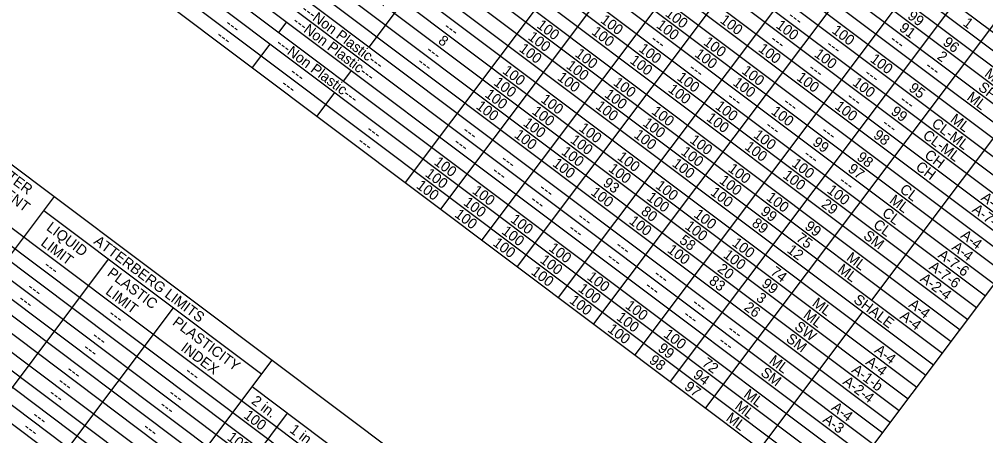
# Model space of a CAD drawing. Extents: x 627484.2 to 627517.5, y 367968.7 to 367996.9.
# Drawn here: x 627506.06 to 627511.18, y 367976.4 to 367978.6 of the extents above; entities that cross this region are included whole.
import ezdxf

# ---------------------------------------------------------------- set-up
doc = ezdxf.new("R2010")
doc.units = 0
doc.layers.add('Default', color=7, linetype='Continuous')

msp = doc.modelspace()

# ---------------------------------------------------------------- linework, layer by layer
at = {"layer": 'Default'}
for p, q in [((627507.3424, 367981.3499), (627511.8177, 367977.9894)), ((627507.3014, 367981.2954), (627511.7767, 367977.9348)), ((627507.2546, 367981.233), (627511.7298, 367977.8725)), ((627507.2078, 367981.1706), (627511.683, 367977.8101)), ((627507.1609, 367981.1082), (627511.6362, 367977.7477)), ((627507.1199, 367981.0537), (627511.5952, 367977.6932)), ((627507.0731, 367980.9913), (627511.5483, 367977.6308)), ((627507.0263, 367980.9289), (627511.5015, 367977.5684)), ((627506.9794, 367980.8665), (627511.4547, 367977.506)), ((627506.9326, 367980.8042), (627511.4078, 367977.4437)), ((627506.8858, 367980.7418), (627511.361, 367977.3813)), ((627506.8448, 367980.6872), (627511.32, 367977.3267)), ((627506.7979, 367980.6248), (627511.2732, 367977.2643)), ((627506.7511, 367980.5625), (627511.2264, 367977.202)), ((627506.7043, 367980.5001), (627511.1795, 367977.1396)), ((627506.6574, 367980.4377), (627511.1327, 367977.0772)), ((627506.6106, 367980.3754), (627511.0858, 367977.0149)), ((627506.5696, 367980.3208), (627511.0449, 367976.9603)), ((627506.5228, 367980.2584), (627510.998, 367976.8979)), ((627506.4759, 367980.196), (627510.9512, 367976.8355)), ((627506.4291, 367980.1337), (627510.9044, 367976.7732)), ((627506.3881, 367980.0791), (627510.8634, 367976.7186)), ((627508.1067, 367977.74), (627509.8689, 367980.0868)), ((627506.3413, 367980.0167), (627510.8165, 367976.6562)), ((627506.2944, 367979.9543), (627510.7697, 367976.5938)), ((627506.2476, 367979.892), (627510.7229, 367976.5315)), ((627506.2008, 367979.8296), (627510.676, 367976.4691)), ((627506.1598, 367979.775), (627510.635, 367976.4145)), ((627507.914, 367978.4577), (627508.9152, 367979.791)), ((627508.2938, 367977.5995), (627509.9506, 367979.806)), ((627506.113, 367979.7126), (627510.5882, 367976.3521)), ((627506.0661, 367979.6503), (627510.5414, 367976.2898)), ((627508.5121, 367977.4356), (627510.1689, 367979.642)), ((627506.0251, 367979.5957), (627510.5004, 367976.2352)), ((627505.9783, 367979.5333), (627510.4536, 367976.1728)), ((627505.9315, 367979.4709), (627510.4067, 367976.1104)), ((627508.6992, 367977.2951), (627510.356, 367979.5015)), ((627505.8846, 367979.4086), (627510.3599, 367976.0481)), ((627508.9175, 367977.1312), (627510.5743, 367979.3376)), ((627509.1046, 367976.9907), (627510.7615, 367979.1971)), ((627509.3229, 367976.8267), (627510.9798, 367979.0332)), ((627510.6092, 367978.9944), (627511.8645, 367978.0518)), ((627509.51, 367976.6862), (627511.1669, 367978.8927)), ((627509.6972, 367976.5457), (627511.4594, 367978.8925)), ((627510.577, 367977.1165), (627511.7479, 367978.6759)), ((627507.4363, 367978.536), (627507.4773, 367978.5906)), ((627505.1779, 367978.4674), (627509.6531, 367975.1069)), ((627507.2958, 367978.3489), (627507.3895, 367978.4737)), ((627510.3599, 367976.0481), (627512.1221, 367978.3948)), ((627507.7794, 367978.2784), (627507.8204, 367978.333)), ((627505.0169, 367978.253), (627509.4921, 367974.8925)), ((627504.97, 367978.1906), (627509.4453, 367974.8301)), ((627507.6389, 367978.0913), (627507.7325, 367978.2161)), ((627504.9291, 367978.136), (627509.4043, 367974.7755)), ((627504.8822, 367978.0736), (627509.3575, 367974.7131)), ((627504.8354, 367978.0113), (627509.3106, 367974.6508)), ((627504.7944, 367977.9567), (627509.2696, 367974.5962)), ((627504.7476, 367977.8943), (627509.2228, 367974.5338)), ((627504.7007, 367977.8319), (627509.176, 367974.4714)), ((627504.6539, 367977.7696), (627509.1291, 367974.4091)), ((627504.6129, 367977.715), (627509.0882, 367974.3545)), ((627504.4574, 367975.2834), (627506.246, 367977.6653)), ((627504.5661, 367977.6526), (627509.0413, 367974.2921)), ((627504.5192, 367977.5902), (627508.9945, 367974.2297)), ((627506.1904, 367977.5912), (627507.3443, 367976.7248)), ((627505.8894, 367976.476), (627506.5334, 367977.3336)), ((627506.2325, 367976.2184), (627506.8765, 367977.076)), ((627509.9856, 367976.3291), (627510.5301, 367977.0542)), ((627505.6113, 367974.417), (627507.3999, 367976.7988)), ((627507.2945, 367976.6585), (627508.885, 367975.4642)), ((627505.7985, 367974.2765), (627507.4816, 367976.518))]:
    msp.add_line(p, q, dxfattribs=at)

# ---------------------------------------------------------------- texts
for s, p in [('---Non Plastic---', (627507.5506, 367978.6475)), ('100', (627509.4783, 367978.6265)), ('99', (627510.7623, 367978.6134)), ('---Non Plastic---', (627507.5038, 367978.5851)), ('100', (627508.7977, 367978.5645)), ('100', (627509.1351, 367978.5916)), ('100', (627509.4314, 367978.5642)), ('100', (627509.7688, 367978.5913)), ('100', (627510.0652, 367978.5638)), ('---', (627510.1284, 367978.6139)), ('1', (627511.056, 367978.5757)), ('---', (627507.1469, 367978.5727)), ('---', (627508.3051, 367978.5564)), ('100', (627509.0882, 367978.5293)), ('100', (627510.3616, 367978.5363)), ('91', (627510.718, 367978.5491)), ('---', (627507.1, 367978.5103)), ('8', (627508.2751, 367978.4814)), ('100', (627508.7509, 367978.5022)), ('---', (627509.401, 367978.4895)), ('100', (627509.681, 367978.4743)), ('---', (627510.0348, 367978.4891)), ('---', (627510.6685, 367978.4887)), ('96', (627510.9492, 367978.473)), ('---Non Plastic---', (627507.416, 367978.4681)), ('---', (627508.2115, 367978.4317)), ('100', (627508.704, 367978.4398)), ('100', (627509.0004, 367978.4123)), ('100', (627509.3378, 367978.4394)), ('100', (627509.6342, 367978.4119)), ('100', (627509.9715, 367978.4391)), ('100', (627510.2679, 367978.4116)), ('---', (627510.3311, 367978.4616)), ('100', (627509.2909, 367978.377)), ('100', (627510.5643, 367978.3841)), ('2', (627510.9187, 367978.3984)), ('---', (627508.1646, 367978.3693)), ('100', (627508.6162, 367978.3228)), ('100', (627508.9536, 367978.3499)), ('---', (627509.6037, 367978.3373)), ('100', (627509.8837, 367978.3221)), ('---', (627510.2375, 367978.3369)), ('---', (627510.8556, 367978.3482)), ('ML', (627511.1703, 367978.3071)), ('---', (627507.4899, 367978.3151)), ('100', (627508.5694, 367978.2605)), ('100', (627508.9067, 367978.2876)), ('100', (627509.2031, 367978.2601)), ('100', (627509.5405, 367978.2872)), ('100', (627509.8369, 367978.2597)), ('100', (627510.1742, 367978.2868)), ('100', (627510.4706, 367978.2594)), ('---', (627510.5339, 367978.3094)), ('---', (627507.4431, 367978.2527)), ('100', (627509.4936, 367978.2248)), ('95', (627510.7686, 367978.2307)), ('SP', (627511.1365, 367978.2349)), ('100', (627508.5225, 367978.1981)), ('100', (627508.8189, 367978.1706)), ('100', (627509.1563, 367978.1977)), ('---', (627509.8064, 367978.185)), ('---', (627510.4402, 367978.1847)), ('---', (627510.721, 367978.1689)), ('ML', (627511.0766, 367978.1823)), ('100', (627508.4757, 367978.1357)), ('100', (627508.7721, 367978.1082)), ('100', (627509.1094, 367978.1354)), ('100', (627509.4058, 367978.1079)), ('100', (627509.7432, 367978.135)), ('100', (627510.0396, 367978.1075)), ('---', (627510.1028, 367978.1576)), ('100', (627510.3769, 367978.1346)), ('99', (627510.6742, 367978.1065)), ('100', (627509.6964, 367978.0726)), ('ML', (627510.9888, 367978.0654)), ('100', (627508.7252, 367978.0459)), ('100', (627509.0216, 367978.0184)), ('100', (627509.359, 367978.0455)), ('---', (627510.0091, 367978.0328)), ('---', (627510.6273, 367978.0442)), ('CL-ML', (627510.8896, 367978.0423)), ('---', (627507.8953, 367978.0106)), ('---', (627508.4043, 367978.0065)), ('100', (627508.6784, 367977.9835)), ('100', (627508.9748, 367977.956)), ('100', (627509.3122, 367977.9831)), ('100', (627509.6085, 367977.9557)), ('100', (627509.9459, 367977.9828)), ('99', (627510.2588, 367977.9429)), ('---', (627510.3055, 367978.0053)), ('98', (627510.581, 367977.9814)), ('CL-ML', (627510.8428, 367977.9799)), ('---', (627507.8485, 367977.9483)), ('---', (627508.3574, 367977.9441)), ('100', (627509.8991, 367977.9204)), ('WATER', (627505.8921, 367977.8322)), ('100', (627508.9279, 367977.8937)), ('100', (627509.2243, 367977.8662)), ('100', (627509.5617, 367977.8933)), ('---', (627510.2119, 367977.8806)), ('98', (627510.4932, 367977.8644)), ('CH', (627510.8518, 367977.8756)), ('CONTENT', (627505.8061, 367977.7936)), ('100', (627508.2532, 367977.8395)), ('---', (627508.607, 367977.8542)), ('100', (627508.8811, 367977.8313)), ('100', (627509.1775, 367977.8038)), ('100', (627509.5149, 367977.8309)), ('100', (627509.8112, 367977.8034)), ('100', (627510.1486, 367977.8305)), ('97', (627510.4459, 367977.8024)), ('CH', (627510.805, 367977.8132)), ('100', (627508.2064, 367977.7771)), ('---', (627508.5602, 367977.7919)), ('100', (627509.7644, 367977.7411)), ('100', (627510.1018, 367977.7682)), ('100', (627508.1595, 367977.7147)), ('93', (627509.1485, 367977.7281)), ('100', (627509.427, 367977.714)), ('100', (627510.3357, 367977.69)), ('---', (627510.399, 367977.7401)), ('CL', (627510.7208, 367977.6935)), ('100', (627508.4559, 367977.6872)), ('---', (627508.8097, 367977.702)), ('100', (627509.0838, 367977.6791)), ('100', (627509.3802, 367977.6516)), ('100', (627509.7176, 367977.6787)), ('100', (627510.014, 367977.6512)), ('ML', (627510.6668, 367977.6366)), ('A-7-6', (627511.1513, 367977.6507)), ('100', (627508.4091, 367977.6249)), ('---', (627508.7629, 367977.6396)), ('29', (627510.3054, 367977.6153)), ('A-7-6', (627511.1045, 367977.5883)), ('100', (627508.3623, 367977.5625)), ('80', (627509.3496, 367977.577)), ('100', (627509.6298, 367977.5617)), ('99', (627509.9836, 367977.5765)), ('CL', (627510.6271, 367977.5688)), ('LIQUID', (627506.1996, 367977.4918)), ('100', (627508.6586, 367977.535)), ('---', (627509.0124, 367977.5498)), ('100', (627509.2865, 367977.5268)), ('100', (627509.5829, 367977.4994)), ('89', (627509.9368, 367977.5141)), ('99', (627510.2176, 367977.4983)), ('CL', (627510.5803, 367977.5064)), ('100', (627508.6118, 367977.4726)), ('---', (627508.9656, 367977.4874)), ('75', (627510.1715, 367977.4354)), ('SM', (627510.528, 367977.4481)), ('A-4', (627511.0436, 367977.4511)), ('LIMIT', (627506.1697, 367977.4111)), ('ATTERBERG LIMITS', (627506.4501, 367977.4197)), ('100', (627508.565, 367977.4103)), ('100', (627508.8614, 367977.3828)), ('---', (627509.2151, 367977.3976)), ('58', (627509.553, 367977.4243)), ('100', (627509.8325, 367977.4095)), ('A-4', (627510.9967, 367977.3888)), ('100', (627509.4892, 367977.3746)), ('100', (627509.7856, 367977.3472)), ('12', (627510.1238, 367977.3736)), ('ML', (627510.4384, 367977.3325)), ('A-7-6', (627510.923, 367977.3466)), ('100', (627508.8145, 367977.3204)), ('---', (627509.1683, 367977.3352)), ('A-7-6', (627510.8761, 367977.2842)), ('---', (627506.1854, 367977.2923)), ('PLASTIC', (627506.5213, 367977.2502)), ('100', (627508.7677, 367977.2581)), ('100', (627509.0641, 367977.2306)), ('---', (627509.4178, 367977.2454)), ('20', (627509.755, 367977.2726)), ('74', (627510.0358, 367977.2568)), ('ML', (627510.3916, 367977.2701)), ('83', (627509.7098, 367977.2091)), ('99', (627509.9892, 367977.1943)), ('A-2-4', (627510.8292, 367977.222)), ('---', (627506.0976, 367977.1754)), ('LIMIT', (627506.5127, 367977.1535)), ('100', (627509.0172, 367977.1682)), ('---', (627509.371, 367977.183)), ('---', (627506.0508, 367977.113)), ('100', (627508.9704, 367977.1058)), ('100', (627509.2668, 367977.0784)), ('---', (627509.6205, 367977.0931)), ('3', (627509.96, 367977.1187)), ('ML', (627510.2569, 367977.0908)), ('SHALE', (627510.476, 367977.1092)), ('A-4', (627510.7684, 367977.0847)), ('26', (627509.8954, 367977.0696)), ('ML', (627510.2101, 367977.0284)), ('---', (627506.5285, 367977.0347)), ('PLASTICITY', (627506.8675, 367976.9902)), ('100', (627509.2199, 367977.016)), ('---', (627509.5737, 367977.0308)), ('A-4', (627510.7216, 367977.0223)), ('100', (627509.1731, 367976.9536)), ('100', (627509.4695, 367976.9261)), ('---', (627509.8077, 367976.9526)), ('SW', (627510.1628, 367976.9664)), ('---', (627506.4407, 367976.9178)), ('---', (627509.7608, 367976.8903)), ('SM', (627510.1182, 367976.9023)), ('---', (627506.3938, 367976.8554)), ('INDEX', (627506.9118, 367976.8538)), ('99', (627509.4391, 367976.8514)), ('A-4', (627510.5869, 367976.843)), ('98', (627509.3928, 367976.7887)), ('72', (627509.673, 367976.7733)), ('ML', (627510.0286, 367976.7867)), ('A-4', (627510.5401, 367976.7806)), ('---', (627506.306, 367976.7385)), ('SM', (627509.9836, 367976.723)), ('A-1-b', (627510.4662, 367976.7386)), ('---', (627506.9339, 367976.7303)), ('94', (627509.626, 367976.7111)), ('A-2-4', (627510.4194, 367976.6762)), ('---', (627506.2592, 367976.6761)), ('97', (627509.5795, 367976.6485)), ('ML', (627509.894, 367976.6074)), ('---', (627506.2123, 367976.6137)), ('---', (627506.8461, 367976.6133)), ('2 in.', (627507.2855, 367976.5729)), ('---', (627506.7992, 367976.551)), ('ML', (627509.8471, 367976.545)), ('A-4', (627510.3586, 367976.5389)), ('---', (627506.1245, 367976.4968)), ('100', (627507.2449, 367976.4967)), ('ML', (627509.8003, 367976.4827)), ('A-3', (627510.3133, 367976.4754)), ('---', (627506.0777, 367976.4344)), ('---', (627506.7114, 367976.434)), ('1 in.', (627507.4882, 367976.4207)), ('---Non Plastic---', (627505.8691, 367976.4081)), ('100', (627507.1571, 367976.3798))]:
    msp.add_text(s, height=0.055, rotation=323.0968, dxfattribs=at).set_placement(p)

doc.saveas('drawing.dxf')
